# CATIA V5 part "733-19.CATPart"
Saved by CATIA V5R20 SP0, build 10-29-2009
Part number: 733-19
Bounding box of the stored display mesh (mm): x -20 to 20, y -20 to 20, z -23 to 36
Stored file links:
  C:\Users\Utente\Desktop\IO LAVORO\3D X SITO CF\X SITO\733\733-19.CATPart
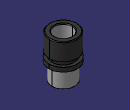
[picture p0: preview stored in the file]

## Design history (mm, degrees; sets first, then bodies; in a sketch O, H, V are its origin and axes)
Set1
  DatumSurface1 to DatumSurface25 "733-19"
Body1 (main body)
